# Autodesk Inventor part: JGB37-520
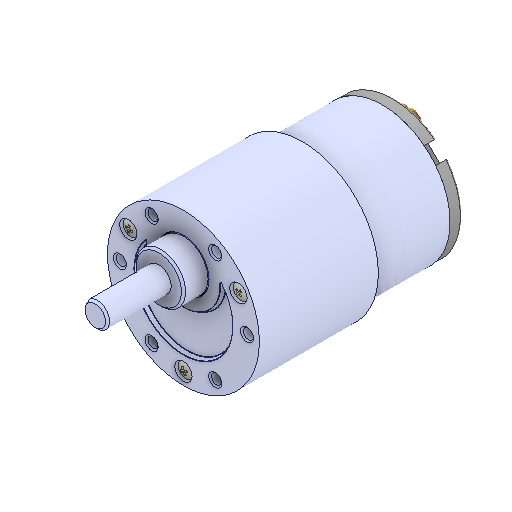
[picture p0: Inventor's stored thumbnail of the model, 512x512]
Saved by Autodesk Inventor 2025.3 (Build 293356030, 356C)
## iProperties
Created: 2017-03
Part Number: JGB37-520
Material: Generico
Description: STEP AP214
Document SubType Name: Modeling
Designer: R5800u
Density: 1 g/cm^3
Appearance: Default
Sending System: SolidWorks 2017
Preprocessor: SwSTEP 2.0
Title: JGB37-520.STEP
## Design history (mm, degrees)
feature "GEARED BODY, MOTOR, JGB37-520_1:1"
feature "DC MOTOR, JGB37-520_2:1"
feature "MOTOR SHAFT, JGB37-520_3:1"
feature "SHAFT COUPLER, JGB37-520_4:1"
feature "COUPLING BRACKET, GEARED BODY TO DC MOTOR, JGB37-520_5:1"
feature "PLASTIC COVER, DC MOTOR, JGB37-520_6:1"
feature "CONNECTION, DC MOTOR, JGB37-520_7:1"
feature "CONNECTION, DC MOTOR, JGB37-520_8:1"
feature "pan cross head_am_B18.6.7M - M2 x 0.4 x 25 Type I Cross Rece"
node "Solido1"
node "Solido2"
node "Solido3"
node "Solido4"
node "Solido5"
node "Solido6"
node "Solido7"
node "Solido8"
node "Solido9"
node "Solido10"
node "Solido11"
